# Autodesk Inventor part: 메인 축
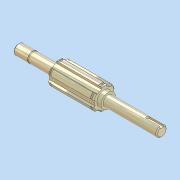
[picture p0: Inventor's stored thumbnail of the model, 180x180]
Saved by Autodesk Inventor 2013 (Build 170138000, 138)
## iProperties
Company: 한국ATC센터
Created: 2014-07
Part Number: 메인 축
Document SubType Name: 모델링
Designer: KYOUNG IL JANG
Mass: 21.4462 g
Surface Area: 72.5109 cm^2
Volume: 21.4462 cm^3
Density: 1 g/cm^3
Material: 일반
변환 표준: STEP AP214IS
파일 이름: C:\Users\SeoGD\Desktop\?쒗뿕\硫붿씤 異?.stp
전처리기: Build: 253, Release: 2010 SP1 - Date: Wed 07/29/2009
전송 단위: 밀리미터
불확실성: 0.01
Author: KYOUNG IL JANG
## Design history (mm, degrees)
sketch "스케치1"
  geometry: L1 (-69.5, 0)-(69.5, 0); L2 (69.5, 0)-(69.5, 5); L3 (69.5, 5)-(55.5, 5); L4 (55.5, 5)-(55.5, 4.8); L5 (55.5, 4.8)-(54.35, 4.8); L6 (54.35, 4.8)-(54.35, 5); L7 (54.35, 5)-(30.5, 5); L8 (30.5, 5)-(30.5, 9); L9 (30.5, 9)-(-13.5, 9); L10 (-13.5, 9)-(-13.5, 7); L11 (-13.5, 7)-(-17.5, 7); L12 (-17.5, 7)-(-17.5, 5); L13 (-17.5, 5)-(-69.5, 5); L14 (-69.5, 5)-(-69.5, 0); 2 further points
  constraints: 28 end point, 9 parallel, 4 collinear, 2 perpendicular, 1 coincident, 1 horizontal, 1 midpoint
  dimensions: "d2" = 1.15 distance between parallel lines of L6 L4; "d3" = 10 diameter of L3 L1; "d4" = 9.6 diameter of L5 L1; "d6" = 44 distance between parallel lines of L10 L8; "d7" = 4 distance between parallel lines of L12 L10; "d8" = 14 diameter of L11 L1; "d9" = 18 diameter of L9 L1; "d33" = 52 distance from line of L12.end L14; "d37" = 39 distance between parallel lines of L8 L2; "d38" = 14 distance between parallel lines of L2 L4
revolve "회전1" sketch "스케치1" stored, may be unused: angle "d10" = 90 deg
sketch "스케치2"
  geometry: L1 (2.5, 10.712)-(2.5, 8.646); L2 (-2.5, 10.712)-(-2.5, 8.646); A1 r 9 centre (0, 0) between (2.5, 8.646) and (-2.5, 8.646) reference; A2 r 11 centre (0, 0) between (2.5, 10.712) and (-2.5, 10.712); 1 further point
  constraints: 4 end point, 4 point on circle, 2 parallel, 1 centre point, 1 coincident, 1 vertical
  dimensions: "d11" = 22 diameter of A2; "d12" = 5 distance between parallel lines of L1 L2
extrude "돌출1" join sketch "스케치2" stored distance "d13" = 10; taper "d14" = 0 deg
chamfer "모따기1" distance "d15" = 1; stored, may be unused: second distance "d16" = 2, angle "d17" = 45 deg
node "작업 평면1"
node "작업 평면2"
sketch "스케치3"
  geometry: L1 (2.5, 10.712)-(2.5, 10.198); L2 (-2.5, 10.712)-(-2.5, 10.198); A1 r 11 centre (0, 0) between (2.5, 10.712) and (-2.5, 10.712) reference; A2 r 10.5 centre (0, 0) between (2.5, 10.198) and (-2.5, 10.198); 1 further point
  constraints: 4 end point, 2 point on circle, 1 centre point, 1 coincident, 1 parallel, 1 vertical
  dimensions: "d19" = 21 diameter of A2
extrude "돌출2" cut sketch "스케치3" distance "d20" = 1.35; taper "d21" = 0 deg
node "작업 평면3"
sketch "스케치4"
  geometry: L1 (-26, -5)-(-26, 5) reference; L2 (-26, 1.5)-(-12.5, 1.5); L3 (-12.5, -1.5)-(-26, -1.5); A1 r 1.5 centre (-12.5, 0) between (-12.5, -1.5) and (-12.5, 1.5); 2 further points
  constraints: 4 end point, 2 perpendicular, 2 point on circle, 2 point on line, 2 tangent, 1 centre point, 1 horizontal alignment, 1 midpoint
  dimensions: "d25" = 3 distance between parallel lines of L3 L2; "d26" = 15 dimension on A1 L1
extrude "돌출3" cut sketch "스케치4" distance "d27" = 1.8; taper "d28" = 0 deg
chamfer "모따기2" distance "d29" = 1; stored, may be unused: second distance "d30" = 2, angle "d31" = 45 deg
node "솔리드1"
node "솔리드 본체"
node "곡면 본체"
mirror "대칭1"
pattern_circular "원형 패턴1" dims "d23" = 360 deg
node "솔리드2"
other parameters: "d18" = -1.65
